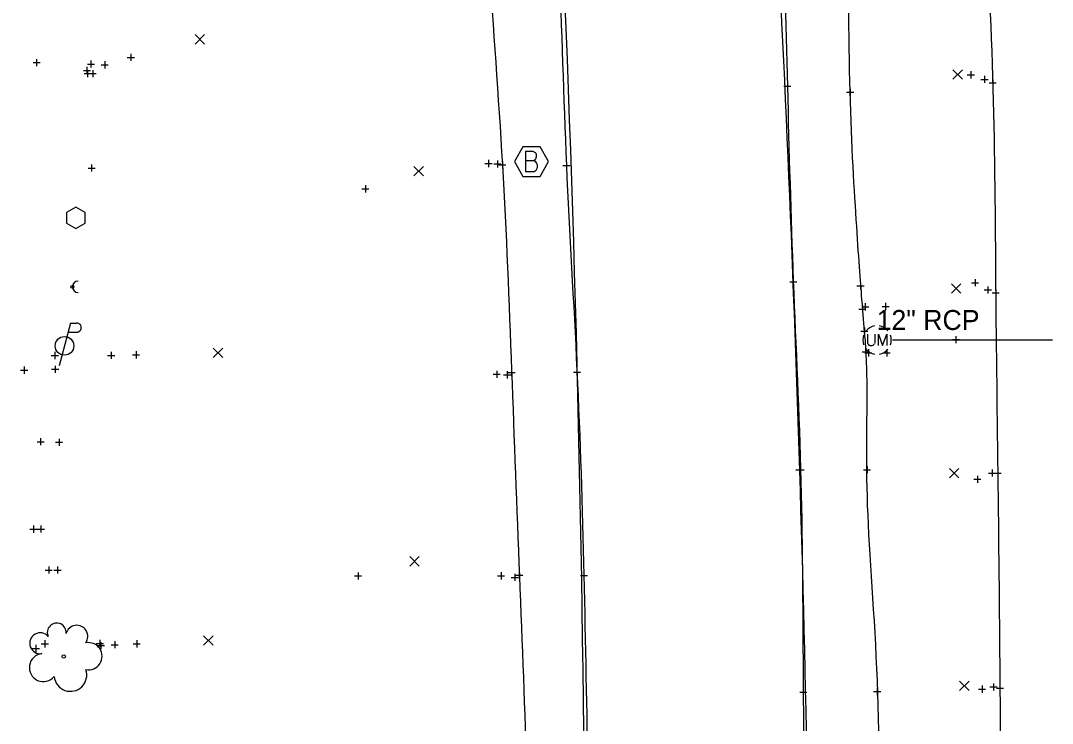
# Model space of a CAD drawing. Extents: x 2188719 to 2189819, y 654569 to 659504.
# Drawn here: x 2189673.8 to 2189818.6, y 657767.3 to 657865.9 of the extents above; entities that cross this region are included whole.
import ezdxf

# ---------------------------------------------------------------- set-up
doc = ezdxf.new("R2010")
doc.units = 0
for name, color, linetype in [('DR_X_Elev_Flow', 7, 'Continuous'), ('DR_X_Storm_Sewer', 7, 'Continuous'), ('DR_X_Text', 7, 'Continuous'), ('PM_X_Edge_Line', 7, 'Continuous'), ('PM_X_Transverse_Line', 7, 'Continuous'), ('PV_X_EOP', 7, 'Continuous'), ('PV_X_Shoulder', 7, 'Continuous'), ('RD_X_Cells', 7, 'Continuous'), ('SV_X_Random_Point', 7, 'Continuous'), ('SV_X_Shot_Marker', 7, 'Continuous'), ('UT_X_Electric_Cells', 7, 'Continuous'), ('UT_X_Misc_Cells', 7, 'Continuous'), ('UT_X_Unknown_Cells', 7, 'Continuous'), ('VG_X_Cells', 7, 'Continuous')]:
    doc.layers.add(name, color=color, linetype=linetype)

msp = doc.modelspace()

# ---------------------------------------------------------------- linework, layer by layer
at = {"layer": 'DR_X_Elev_Flow'}
for p, q in [((2189805.05, 657821.68), (2189805.05, 657820.68)), ((2189804.55, 657821.18), (2189805.55, 657821.18)), ((2189805.05, 657821.18), (2189805.05, 657821.18))]:
    msp.add_line(p, q, dxfattribs=at)
at = {"layer": 'DR_X_Storm_Sewer'}
msp.add_line((2189796.14, 657821.13), (2189818.57, 657821.13), dxfattribs=at)
at = {"layer": 'PM_X_Edge_Line'}
msp.add_open_spline([(2189715.92, 658416.15), (2189719.55, 658398.42), (2189727.31, 658355.37), (2189741.15, 658285.79), (2189752.08, 658199.49), (2189764.73, 658083.92), (2189776.67, 657949.48), (2189785.57, 657773.05), (2189784.87, 657651.45), (2189781.91, 657575.63)], degree=3, dxfattribs=at)
at = {"layer": 'PM_X_Transverse_Line'}
msp.add_open_spline([(2189687.91, 658347.82), (2189695.6, 658312.27), (2189724.53, 658165.17), (2189751.08, 657933.72), (2189754.2, 657738.17), (2189752.07, 657655.83)], degree=3, dxfattribs=at)
at = {"layer": 'PV_X_EOP'}
for points in [[(2189715.65, 658416.09), (2189717.36, 658407.13), (2189721.67, 658389.5), (2189726.25, 658363.76), (2189732.27, 658338.61), (2189735.95, 658313.21), (2189740.83, 658286.81), (2189744.4, 658258.95), (2189748.43, 658232.12), (2189751.61, 658205.72), (2189755.02, 658180.62), (2189757.39, 658155.27), (2189760.52, 658129.99), (2189762.73, 658103.87), (2189765.52, 658076.79), (2189767.84, 658049.53), (2189770.28, 658023.15), (2189773.03, 657997.24), (2189774.6, 657969.67), (2189777.01, 657941.26), (2189778.8, 657911.99), (2189780.69, 657884.09), (2189781.4, 657856.58), (2189782.11, 657829.65), (2189783.53, 657801.33), (2189783.56, 657772.66), (2189783.96, 657743.23), (2189783.95, 657715.3), (2189783.44, 657687.6), (2189783.88, 657660.21), (2189783.01, 657632.25), (2189782.93, 657604.05), (2189782.64, 657585.12), (2189782.5, 657575.65)], [(2189686.87, 658347.88), (2189688.95, 658339.56), (2189693.17, 658321.78), (2189697.87, 658294.9), (2189703.7, 658267.62), (2189707.98, 658241.03), (2189713.11, 658215.13), (2189716.61, 658188.45), (2189721.68, 658160.42), (2189724.61, 658131.33), (2189729.42, 658103.12), (2189732.17, 658074.94), (2189735.91, 658046.42), (2189738.42, 658016.97), (2189741.68, 657987.88), (2189743.15, 657958.86), (2189745.92, 657930.4), (2189747.37, 657902.49), (2189749.54, 657874.27), (2189750.21, 657845.72), (2189752.04, 657816.78), (2189752.93, 657788.08), (2189753.38, 657759.61), (2189754.01, 657732.65), (2189754.13, 657706.9), (2189754.02, 657681.8), (2189752.87, 657664.76), (2189752.08, 657656.03)]]:
    msp.add_open_spline(points, degree=3, dxfattribs=at)
at = {"layer": 'PV_X_Shoulder'}
for points in [[(2189678.17, 658346.51), (2189680.12, 658338.02), (2189683.83, 658320.14), (2189688.68, 658299.1), (2189690.22, 658284.76), (2189692.33, 658279.09), (2189693.11, 658275.51), (2189692.87, 658271.06), (2189696.13, 658259.46), (2189698.82, 658239.7), (2189703.41, 658214.08), (2189707.68, 658187.35), (2189711.85, 658159.43), (2189715.66, 658130.84), (2189719.89, 658102.92), (2189722.84, 658074.64), (2189726.21, 658045.96), (2189729.3, 658016.08), (2189731.79, 657986.57), (2189734.56, 657957.49), (2189736.24, 657929.57), (2189738.31, 657902.49), (2189739.34, 657874.4), (2189741.63, 657845.81), (2189742.72, 657816.8), (2189743.78, 657788), (2189744.99, 657759.47), (2189745.29, 657733.99), (2189744.96, 657716.97), (2189745.15, 657707.52), (2189744.91, 657697.88), (2189745.01, 657680.84), (2189744.6, 657665.71), (2189744.35, 657657.17)], [(2189801.82, 658044.25), (2189802.16, 658038.16), (2189802.98, 658023.46), (2189804.8, 657999.54), (2189805.65, 657970.94), (2189806.89, 657942.16), (2189807.79, 657912.49), (2189808.97, 657884.8), (2189810.47, 657856.11), (2189810.57, 657829.12), (2189810.94, 657800.81), (2189811.25, 657772.16), (2189811.38, 657742.5), (2189812.33, 657713.83), (2189811.88, 657686.44), (2189812.29, 657658.62), (2189811.35, 657630.96), (2189811.25, 657602.53), (2189810.6, 657583.97), (2189810.21, 657574.36)], [(2189779.92, 658011.44), (2189780.4, 658006.73), (2189781.74, 657993.22), (2189782.93, 657968.66), (2189785.63, 657948.14), (2189785.75, 657935.25), (2189785.75, 657932.35), (2189787.48, 657924.59), (2189786.45, 657908.18), (2189789.99, 657883.89), (2189789.91, 657856.04), (2189791.07, 657836.67), (2189791.89, 657825.52), (2189792.21, 657822.44), (2189792.71, 657814.94), (2189792.19, 657798.04), (2189794.52, 657772.31), (2189793.99, 657742.26), (2189794.17, 657721.57), (2189794.66, 657709.58), (2189794.51, 657706.15), (2189795.19, 657698.52), (2189794.06, 657682.99), (2189795.47, 657659.17), (2189794.67, 657631.4), (2189794.75, 657603.18), (2189794.52, 657584.46), (2189794.41, 657574.89)]]:
    msp.add_open_spline(points, degree=3, dxfattribs=at)
at = {"layer": 'RD_X_Cells'}
for p, q in [((2189744.31, 657848.23), (2189743.11, 657846.15)), ((2189746.71, 657848.23), (2189744.31, 657848.23)), ((2189747.91, 657846.15), (2189746.71, 657848.23)), ((2189743.11, 657846.15), (2189744.31, 657844.08)), ((2189746.71, 657844.08), (2189747.91, 657846.15)), ((2189744.31, 657844.08), (2189746.71, 657844.08))]:
    msp.add_line(p, q, dxfattribs=at)
for points in [[(2189745.87, 657846.28), (2189745.98, 657846.39), (2189746.05, 657846.45), (2189746.09, 657846.52), (2189746.12, 657846.56), (2189746.16, 657846.65), (2189746.18, 657846.72), (2189746.23, 657846.87), (2189746.23, 657846.94), (2189746.23, 657847.02), (2189746.2, 657847.16), (2189746.16, 657847.27), (2189746.09, 657847.36), (2189745.98, 657847.44), (2189745.89, 657847.49), (2189745.85, 657847.51), (2189745.74, 657847.55), (2189744.66, 657847.55), (2189744.66, 657844.75), (2189745.87, 657844.75), (2189746.03, 657844.84), (2189746.16, 657844.95), (2189746.27, 657845.13), (2189746.34, 657845.33), (2189746.36, 657845.53), (2189746.36, 657845.66), (2189746.31, 657845.79), (2189746.23, 657845.99), (2189746.12, 657846.12), (2189745.87, 657846.28), (2189744.66, 657846.28)], [(2189680.3, 657837.51), (2189681.59, 657836.76), (2189682.89, 657837.51), (2189682.89, 657839.01), (2189681.59, 657839.76), (2189680.3, 657839.01), (2189680.3, 657837.51)]]:
    msp.add_lwpolyline(points, dxfattribs=at)
at = {"layer": 'SV_X_Random_Point'}
for p, q in [((2189698.33, 657862.63), (2189699.66, 657863.97)), ((2189698.33, 657863.97), (2189699.66, 657862.63)), ((2189804.63, 657857.7), (2189805.96, 657859.03)), ((2189804.63, 657859.03), (2189805.96, 657857.7)), ((2189729.02, 657844.13), (2189730.35, 657845.47)), ((2189729.02, 657845.47), (2189730.35, 657844.13)), ((2189804.41, 657827.68), (2189805.75, 657829.01)), ((2189804.41, 657829.01), (2189805.75, 657827.68)), ((2189700.87, 657818.66), (2189702.2, 657819.99)), ((2189700.87, 657819.99), (2189702.2, 657818.66)), ((2189804.13, 657801.77), (2189805.46, 657803.11)), ((2189804.13, 657803.11), (2189805.46, 657801.77)), ((2189728.43, 657789.39), (2189729.76, 657790.73)), ((2189728.43, 657790.73), (2189729.76, 657789.39)), ((2189699.5, 657778.31), (2189700.84, 657779.64)), ((2189699.5, 657779.64), (2189700.84, 657778.31)), ((2189805.55, 657771.95), (2189806.88, 657773.28)), ((2189805.55, 657773.28), (2189806.88, 657771.95))]:
    msp.add_line(p, q, dxfattribs=at)
at = {"layer": 'SV_X_Shot_Marker'}
for p, q in [((2189676.09, 657860.54), (2189676.09, 657859.54)), ((2189683.71, 657860.33), (2189683.71, 657859.33)), ((2189688.81, 657860.77), (2189689.81, 657860.77)), ((2189689.31, 657861.27), (2189689.31, 657860.27)), ((2189689.31, 657860.77), (2189689.31, 657860.77)), ((2189675.59, 657860.04), (2189676.59, 657860.04)), ((2189676.09, 657860.04), (2189676.09, 657860.04)), ((2189682.65, 657858.93), (2189683.65, 657858.93)), ((2189683.15, 657859.43), (2189683.15, 657858.43)), ((2189683.15, 657858.93), (2189683.15, 657858.93)), ((2189683.21, 657859.83), (2189684.21, 657859.83)), ((2189683.25, 657858.99), (2189683.25, 657857.99)), ((2189683.71, 657859.83), (2189683.71, 657859.83)), ((2189683.96, 657858.99), (2189683.96, 657857.99)), ((2189685.14, 657859.73), (2189686.14, 657859.73)), ((2189685.14, 657859.73), (2189686.14, 657859.73)), ((2189685.64, 657860.23), (2189685.64, 657859.23)), ((2189685.64, 657860.23), (2189685.64, 657859.23)), ((2189685.64, 657859.73), (2189685.64, 657859.73)), ((2189685.64, 657859.73), (2189685.64, 657859.73)), ((2189682.75, 657858.49), (2189683.75, 657858.49)), ((2189683.25, 657858.49), (2189683.25, 657858.49)), ((2189683.46, 657858.49), (2189684.46, 657858.49)), ((2189683.96, 657858.49), (2189683.96, 657858.49)), ((2189806.63, 657858.32), (2189807.63, 657858.32)), ((2189807.13, 657858.82), (2189807.13, 657857.82)), ((2189807.13, 657858.32), (2189807.13, 657858.32)), ((2189808.55, 657857.68), (2189809.55, 657857.68)), ((2189809.05, 657858.18), (2189809.05, 657857.18)), ((2189809.05, 657857.68), (2189809.05, 657857.68)), ((2189810.21, 657857.68), (2189810.21, 657856.68)), ((2189780.9, 657856.74), (2189781.9, 657856.74)), ((2189781.4, 657857.24), (2189781.4, 657856.24)), ((2189781.4, 657856.74), (2189781.4, 657856.74)), ((2189790.2, 657856.37), (2189790.2, 657855.37)), ((2189809.71, 657857.18), (2189810.71, 657857.18)), ((2189810.21, 657857.18), (2189810.21, 657857.18)), ((2189789.7, 657855.87), (2189790.7, 657855.87)), ((2189790.2, 657855.87), (2189790.2, 657855.87)), ((2189738.98, 657845.88), (2189739.98, 657845.88)), ((2189739.48, 657846.38), (2189739.48, 657845.38)), ((2189739.48, 657845.88), (2189739.48, 657845.88)), ((2189740.73, 657846.32), (2189740.73, 657845.32)), ((2189741.43, 657846.2), (2189741.43, 657845.2)), ((2189750.41, 657846.09), (2189750.41, 657845.09)), ((2189683.31, 657845.24), (2189684.31, 657845.24)), ((2189683.81, 657845.74), (2189683.81, 657844.74)), ((2189683.81, 657845.24), (2189683.81, 657845.24)), ((2189740.23, 657845.82), (2189741.23, 657845.82)), ((2189740.73, 657845.82), (2189740.73, 657845.82)), ((2189740.93, 657845.7), (2189741.93, 657845.7)), ((2189741.43, 657845.7), (2189741.43, 657845.7)), ((2189749.91, 657845.59), (2189750.91, 657845.59)), ((2189750.41, 657845.59), (2189750.41, 657845.59)), ((2189721.71, 657842.32), (2189722.71, 657842.32)), ((2189722.21, 657842.82), (2189722.21, 657841.82)), ((2189722.21, 657842.32), (2189722.21, 657842.32)), ((2189781.73, 657829.3), (2189782.73, 657829.3)), ((2189782.23, 657829.8), (2189782.23, 657828.8)), ((2189782.23, 657829.3), (2189782.23, 657829.3)), ((2189791.16, 657828.71), (2189792.16, 657828.71)), ((2189791.66, 657829.21), (2189791.66, 657828.21)), ((2189791.66, 657828.71), (2189791.66, 657828.71)), ((2189807.22, 657829.16), (2189808.22, 657829.16)), ((2189807.72, 657829.66), (2189807.72, 657828.66)), ((2189807.72, 657829.16), (2189807.72, 657829.16)), ((2189809.51, 657828.64), (2189809.51, 657827.64)), ((2189809.01, 657828.14), (2189810.01, 657828.14)), ((2189809.51, 657828.14), (2189809.51, 657828.14)), ((2189810.13, 657827.72), (2189811.13, 657827.72)), ((2189810.63, 657828.22), (2189810.63, 657827.22)), ((2189810.63, 657827.72), (2189810.63, 657827.72)), ((2189791.83, 657825.78), (2189792.83, 657825.78)), ((2189791.92, 657825.96), (2189791.92, 657824.96)), ((2189792.33, 657826.28), (2189792.33, 657825.28)), ((2189792.33, 657825.78), (2189792.33, 657825.78)), ((2189794.68, 657825.82), (2189795.68, 657825.82)), ((2189795.18, 657826.32), (2189795.18, 657825.32)), ((2189795.18, 657825.82), (2189795.18, 657825.82)), ((2189791.42, 657825.46), (2189792.42, 657825.46)), ((2189791.92, 657825.46), (2189791.92, 657825.46)), ((2189792.2, 657822.88), (2189792.2, 657821.88)), ((2189791.7, 657822.38), (2189792.7, 657822.38)), ((2189792.2, 657822.38), (2189792.2, 657822.38)), ((2189792.4, 657819.97), (2189792.4, 657818.97)), ((2189792.76, 657819.83), (2189792.76, 657818.83)), ((2189795.34, 657819.82), (2189795.34, 657818.82)), ((2189678.15, 657818.95), (2189679.15, 657818.95)), ((2189678.65, 657819.45), (2189678.65, 657818.45)), ((2189678.65, 657818.95), (2189678.65, 657818.95)), ((2189686.04, 657818.97), (2189687.04, 657818.97)), ((2189686.04, 657818.97), (2189687.04, 657818.97)), ((2189686.04, 657818.97), (2189687.04, 657818.97)), ((2189686.54, 657819.47), (2189686.54, 657818.47)), ((2189686.54, 657819.47), (2189686.54, 657818.47)), ((2189686.54, 657819.47), (2189686.54, 657818.47)), ((2189686.54, 657818.97), (2189686.54, 657818.97)), ((2189686.54, 657818.97), (2189686.54, 657818.97)), ((2189686.54, 657818.97), (2189686.54, 657818.97)), ((2189689.54, 657819.05), (2189690.54, 657819.05)), ((2189690.04, 657819.55), (2189690.04, 657818.55)), ((2189690.04, 657819.05), (2189690.04, 657819.05)), ((2189791.9, 657819.47), (2189792.9, 657819.47)), ((2189792.26, 657819.33), (2189793.26, 657819.33)), ((2189792.4, 657819.47), (2189792.4, 657819.47)), ((2189792.76, 657819.33), (2189792.76, 657819.33)), ((2189794.84, 657819.32), (2189795.84, 657819.32)), ((2189795.34, 657819.32), (2189795.34, 657819.32)), ((2189674.35, 657817.39), (2189674.35, 657816.39)), ((2189678.19, 657817.02), (2189679.19, 657817.02)), ((2189678.19, 657817.02), (2189679.19, 657817.02)), ((2189678.69, 657817.52), (2189678.69, 657816.52)), ((2189678.69, 657817.52), (2189678.69, 657816.52)), ((2189678.69, 657817.02), (2189678.69, 657817.02)), ((2189678.69, 657817.02), (2189678.69, 657817.02)), ((2189742.72, 657817.07), (2189742.72, 657816.07)), ((2189751.89, 657817.13), (2189751.89, 657816.13)), ((2189673.85, 657816.89), (2189674.85, 657816.89)), ((2189674.35, 657816.89), (2189674.35, 657816.89)), ((2189740.13, 657816.31), (2189741.13, 657816.31)), ((2189740.63, 657816.81), (2189740.63, 657815.81)), ((2189740.63, 657816.31), (2189740.63, 657816.31)), ((2189741.59, 657816.23), (2189742.59, 657816.23)), ((2189742.09, 657816.73), (2189742.09, 657815.73)), ((2189742.09, 657816.23), (2189742.09, 657816.23)), ((2189742.22, 657816.57), (2189743.22, 657816.57)), ((2189742.72, 657816.57), (2189742.72, 657816.57)), ((2189751.39, 657816.63), (2189752.39, 657816.63)), ((2189751.89, 657816.63), (2189751.89, 657816.63)), ((2189676.15, 657806.85), (2189677.15, 657806.85)), ((2189676.65, 657807.35), (2189676.65, 657806.35)), ((2189676.65, 657806.85), (2189676.65, 657806.85)), ((2189678.74, 657806.78), (2189679.74, 657806.78)), ((2189679.24, 657807.28), (2189679.24, 657806.28)), ((2189679.24, 657806.78), (2189679.24, 657806.78)), ((2189782.59, 657802.92), (2189783.59, 657802.92)), ((2189782.75, 657802.92), (2189783.75, 657802.92)), ((2189783.09, 657803.42), (2189783.09, 657802.42)), ((2189783.09, 657802.92), (2189783.09, 657802.92)), ((2189783.25, 657803.42), (2189783.25, 657802.42)), ((2189783.25, 657802.92), (2189783.25, 657802.92)), ((2189792.07, 657802.92), (2189793.07, 657802.92)), ((2189792.57, 657803.42), (2189792.57, 657802.42)), ((2189792.57, 657802.92), (2189792.57, 657802.92)), ((2189809.63, 657802.45), (2189810.63, 657802.45)), ((2189810.13, 657802.95), (2189810.13, 657801.95)), ((2189810.13, 657802.45), (2189810.13, 657802.45)), ((2189810.41, 657802.45), (2189811.41, 657802.45)), ((2189810.91, 657802.95), (2189810.91, 657801.95)), ((2189810.91, 657802.45), (2189810.91, 657802.45)), ((2189807.55, 657801.58), (2189808.55, 657801.58)), ((2189808.05, 657802.08), (2189808.05, 657801.08)), ((2189808.05, 657801.58), (2189808.05, 657801.58)), ((2189675.16, 657794.58), (2189676.16, 657794.58)), ((2189675.66, 657795.08), (2189675.66, 657794.08)), ((2189675.66, 657794.58), (2189675.66, 657794.58)), ((2189676.2, 657794.6), (2189677.2, 657794.6)), ((2189676.7, 657795.1), (2189676.7, 657794.1)), ((2189676.7, 657794.6), (2189676.7, 657794.6)), ((2189677.29, 657788.85), (2189678.29, 657788.85)), ((2189677.79, 657789.35), (2189677.79, 657788.35)), ((2189677.79, 657788.85), (2189677.79, 657788.85)), ((2189678.52, 657788.85), (2189679.52, 657788.85)), ((2189679.02, 657789.35), (2189679.02, 657788.35)), ((2189679.02, 657788.85), (2189679.02, 657788.85)), ((2189720.68, 657788.02), (2189721.68, 657788.02)), ((2189721.18, 657788.52), (2189721.18, 657787.52)), ((2189721.18, 657788.02), (2189721.18, 657788.02)), ((2189740.73, 657788.03), (2189741.73, 657788.03)), ((2189741.23, 657788.53), (2189741.23, 657787.53)), ((2189741.23, 657788.03), (2189741.23, 657788.03)), ((2189743.16, 657788.32), (2189743.16, 657787.32)), ((2189743.3, 657788.11), (2189744.3, 657788.11)), ((2189743.8, 657788.61), (2189743.8, 657787.61)), ((2189743.8, 657788.11), (2189743.8, 657788.11)), ((2189752.36, 657788.09), (2189753.36, 657788.09)), ((2189752.86, 657788.59), (2189752.86, 657787.59)), ((2189752.86, 657788.09), (2189752.86, 657788.09)), ((2189742.66, 657787.82), (2189743.66, 657787.82)), ((2189743.16, 657787.82), (2189743.16, 657787.82)), ((2189675.48, 657777.84), (2189676.48, 657777.84)), ((2189675.98, 657778.34), (2189675.98, 657777.34)), ((2189675.98, 657777.84), (2189675.98, 657777.84)), ((2189676.74, 657778.49), (2189677.74, 657778.49)), ((2189677.24, 657778.99), (2189677.24, 657777.99)), ((2189677.24, 657778.49), (2189677.24, 657778.49)), ((2189684.46, 657778.54), (2189685.46, 657778.54)), ((2189684.61, 657778.25), (2189685.61, 657778.25)), ((2189684.96, 657779.04), (2189684.96, 657778.04)), ((2189684.96, 657778.54), (2189684.96, 657778.54)), ((2189685.11, 657778.75), (2189685.11, 657777.75)), ((2189685.11, 657778.25), (2189685.11, 657778.25)), ((2189686.55, 657778.38), (2189687.55, 657778.38)), ((2189686.55, 657778.38), (2189687.55, 657778.38)), ((2189687.05, 657778.88), (2189687.05, 657777.88)), ((2189687.05, 657778.88), (2189687.05, 657777.88)), ((2189687.05, 657778.38), (2189687.05, 657778.38)), ((2189687.05, 657778.38), (2189687.05, 657778.38)), ((2189689.63, 657778.5), (2189690.63, 657778.5)), ((2189690.13, 657779), (2189690.13, 657778)), ((2189690.13, 657778.5), (2189690.13, 657778.5)), ((2189783.63, 657772.24), (2189783.63, 657771.24)), ((2189793.99, 657772.29), (2189793.99, 657771.29)), ((2189808.21, 657772.14), (2189809.21, 657772.14)), ((2189808.71, 657772.64), (2189808.71, 657771.64)), ((2189808.71, 657772.14), (2189808.71, 657772.14)), ((2189809.82, 657772.45), (2189810.82, 657772.45)), ((2189810.32, 657772.95), (2189810.32, 657771.95)), ((2189810.32, 657772.45), (2189810.32, 657772.45)), ((2189810.72, 657772.26), (2189811.72, 657772.26)), ((2189811.22, 657772.76), (2189811.22, 657771.76)), ((2189811.22, 657772.26), (2189811.22, 657772.26)), ((2189783.13, 657771.74), (2189784.13, 657771.74)), ((2189783.63, 657771.74), (2189783.63, 657771.74)), ((2189793.49, 657771.79), (2189794.49, 657771.79)), ((2189793.99, 657771.79), (2189793.99, 657771.79))]:
    msp.add_line(p, q, dxfattribs=at)
at = {"layer": 'UT_X_Electric_Cells'}
for p, q in [((2189680.85, 657823.5), (2189679.25, 657817.5)), ((2189680.85, 657823.5), (2189681.7, 657823.5)), ((2189680.51, 657822.22), (2189681.7, 657822.22))]:
    msp.add_line(p, q, dxfattribs=at)
msp.add_circle((2189680, 657820.3), 1.3, dxfattribs=at)
msp.add_arc((2189681.72, 657822.86), 0.638, 268.8767, 91.1233, dxfattribs=at)
at = {"layer": 'UT_X_Misc_Cells'}
msp.add_circle((2189681.11, 657828.59), 0.2, dxfattribs=at)
msp.add_arc((2189681.91, 657828.59), 0.8, 90, 270, dxfattribs=at)
at = {"layer": 'UT_X_Unknown_Cells'}
for p, q in [((2189792.64, 657821.93), (2189792.64, 657820.66)), ((2189793.65, 657821.93), (2189793.65, 657820.66)), ((2189793.98, 657821.12), (2189793.98, 657821.12))]:
    msp.add_line(p, q, dxfattribs=at)
msp.add_lwpolyline([(2189794.17, 657820.33), (2189794.17, 657821.93), (2189794.76, 657820.33), (2189795.35, 657821.93), (2189795.35, 657820.33)], dxfattribs=at)
for centre, radius, start, end in [((2189793.98, 657821.12), 2, 100.0806, 140.0721), ((2189793.98, 657821.12), 2, 40.0577, 80.1061), ((2189793.98, 657821.12), 2, 160.0169, 200.0392), ((2189793.98, 657821.12), 2, 340.0169, 20.0392), ((2189793.98, 657821.12), 2, 220.0577, 260.0473), ((2189793.14, 657820.89), 0.557, 205.1924, 334.8076), ((2189793.98, 657821.12), 2, 280.0114, 320.0264)]:
    msp.add_arc(centre, radius, start, end, dxfattribs=at)
at = {"layer": 'VG_X_Cells'}
msp.add_circle((2189679.9, 657776.72), 0.24, dxfattribs=at)
for centre, radius, start, end in [((2189678.91, 657780.09), 1.32, 354.0047, 205.9741), ((2189681.72, 657779.55), 1.55, 323.83, 165.0376), ((2189676.59, 657778.58), 1.47, 39.0625, 279.5412), ((2189683.36, 657776.76), 1.91, 259.1453, 101.4596), ((2189677.04, 657775.17), 1.97, 96.1722, 320.5737), ((2189680.84, 657774.11), 2.28, 184.9476, 19.4572)]:
    msp.add_arc(centre, radius, start, end, dxfattribs=at)

# ---------------------------------------------------------------- texts
at = {"layer": 'DR_X_Text'}
msp.add_text('12" RCP', height=2.8, dxfattribs=at).set_placement((2189793.92, 657822.53))

doc.saveas('drawing.dxf')
